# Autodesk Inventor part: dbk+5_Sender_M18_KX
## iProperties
Shininess: 20.0
Length Units: 11269
Angle Units: 11279
Time Units: 11290
Mass Units: 11283
Length Display Precision: 2
Angle Display Precision: 2
Part Number: dbk+5_Sender_M18_KX
Material: Nichtrostender Stahl - 440C
Document SubType Name: Modellieren
Description: dbk-4/Sender/M18/K2
Checked By: Alves
Created: 2005-08
Designer: Ohle
Manufacturer: Standard
Standards Organization: Custom
Density: 0.0
Volumn: 0.0
Area: 0.0
PropertySet Name: Model Information
Control State: 0
Master: False
Checked Out: False
BESTELLNUMMER: dbk-4/Sender/M18/K1
ME: ST
Title: dbk-4 Sensoren
Author: Ohle
Comments: keine Bemerkung
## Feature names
1. dbk-4 Sender [Revolution]
2. Extrusion6
3. Extrusion7
